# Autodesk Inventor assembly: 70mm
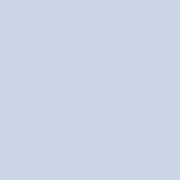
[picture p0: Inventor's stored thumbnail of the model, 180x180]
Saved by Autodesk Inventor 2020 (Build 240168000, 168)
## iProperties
Created: 2020-11
Part Number: 70mm
Document SubType Name: Assembly
Designer: Yolande
Author: Yolande
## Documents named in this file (1)
- D:\Drawing Division\3. Revit Family Files\2. Kraft\70mm.iam
